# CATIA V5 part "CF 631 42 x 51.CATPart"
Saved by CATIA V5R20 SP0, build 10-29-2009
Part number: CF 631 42 x 51
Definition: NONE
Nomenclature: CF 631 42 x 51
Source: Unknown
Description: CF 631 42 x 51
Bounding box of the stored display mesh (mm): x -13 to 38, y -31.5 to 31.5, z -31.5 to 31.5
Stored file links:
  C:\Users\Utente\Desktop\IO LAVORO\3D X SITO CF\X SITO\CF 631\CF 631 42 x 51.CATPart
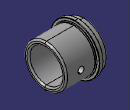
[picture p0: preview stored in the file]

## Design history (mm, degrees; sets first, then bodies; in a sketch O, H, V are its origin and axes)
Body1 "CF 631 42 x 51" (main body)
  Solid1: solid without history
